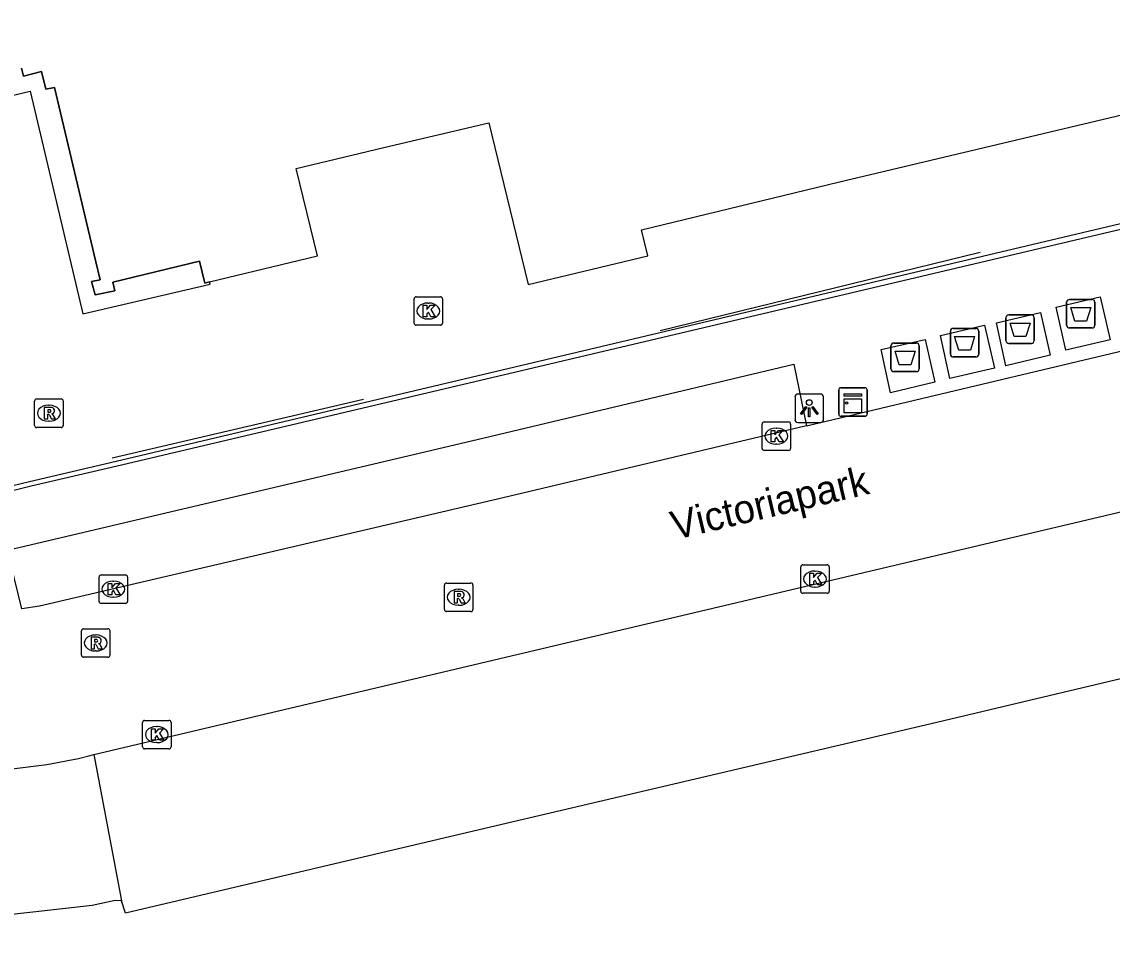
# Model space of a CAD drawing. Extents: x 160676 to 161153, y 383244 to 383713.
# Drawn here: x 160908.82 to 160947.04, y 383443.78 to 383475.88 of the extents above; entities that cross this region are included whole.
import ezdxf

# ---------------------------------------------------------------- set-up
doc = ezdxf.new("R2010")
doc.units = 0
for name, color, linetype in [('IMGEO_Afval_apart_plaats', 7, 'Continuous'), ('IMGEO_Kast', 7, 'Continuous'), ('IMGEO_Kolk', 7, 'Continuous'), ('IMGEO_Lichtpunt', 7, 'Continuous'), ('IMGEO_Lijnafwatering', 7, 'Continuous'), ('IMGEO_Muur', 7, 'Continuous'), ('IMGEO_Openbare_ruimte_label', 7, 'Continuous'), ('IMGEO_Pand', 7, 'Continuous'), ('IMGEO_Pand_overbouw', 7, 'Continuous'), ('IMGEO_Parkeervlak_gesloten', 7, 'Continuous'), ('IMGEO_Rijbaan_lokaal_gesloten', 7, 'Continuous'), ('IMGEO_Rioolput', 7, 'Continuous'), ('IMGEO_Voetpad_gesloten', 7, 'Continuous'), ('IMGEO_Voetpad_open', 7, 'Continuous')]:
    doc.layers.add(name, color=color, linetype=linetype)

msp = doc.modelspace()

# ---------------------------------------------------------------- linework, layer by layer
at = {"layer": 'IMGEO_Afval_apart_plaats'}
for p, q in [((160945.439, 383465.254), (160945.439, 383466.054)), ((160945.439, 383466.054), (160945.439, 383465.254)), ((160945.539, 383466.154), (160946.329, 383466.154)), ((160946.329, 383466.154), (160945.539, 383466.154)), ((160946.429, 383466.054), (160946.429, 383465.254)), ((160946.429, 383465.254), (160946.429, 383466.054)), ((160943.313, 383464.712), (160943.313, 383465.512)), ((160943.313, 383465.512), (160943.313, 383464.712)), ((160943.413, 383465.612), (160944.203, 383465.612)), ((160944.203, 383465.612), (160943.413, 383465.612)), ((160944.303, 383465.512), (160944.303, 383464.712)), ((160944.303, 383464.712), (160944.303, 383465.512)), ((160941.367, 383464.239), (160941.367, 383465.039)), ((160941.367, 383465.039), (160941.367, 383464.239)), ((160941.467, 383465.139), (160942.257, 383465.139)), ((160942.257, 383465.139), (160941.467, 383465.139)), ((160942.357, 383465.039), (160942.357, 383464.239)), ((160942.357, 383464.239), (160942.357, 383465.039)), ((160946.329, 383465.154), (160945.539, 383465.154)), ((160945.539, 383465.154), (160946.329, 383465.154)), ((160939.282, 383463.725), (160939.282, 383464.525)), ((160939.282, 383464.525), (160939.282, 383463.725)), ((160939.382, 383464.625), (160940.172, 383464.625)), ((160940.172, 383464.625), (160939.382, 383464.625)), ((160940.272, 383464.525), (160940.272, 383463.725)), ((160940.272, 383463.725), (160940.272, 383464.525)), ((160944.203, 383464.612), (160943.413, 383464.612)), ((160943.413, 383464.612), (160944.203, 383464.612)), ((160942.257, 383464.139), (160941.467, 383464.139)), ((160941.467, 383464.139), (160942.257, 383464.139)), ((160940.172, 383463.625), (160939.382, 383463.625)), ((160939.382, 383463.625), (160940.172, 383463.625))]:
    msp.add_line(p, q, dxfattribs=at)
for points in [[(160945.582, 383465.868), (160946.286, 383465.868), (160946.137, 383465.398), (160945.731, 383465.398), (160945.582, 383465.868)], [(160943.456, 383465.326), (160944.16, 383465.326), (160944.011, 383464.856), (160943.605, 383464.856), (160943.456, 383465.326)], [(160941.51, 383464.853), (160942.214, 383464.853), (160942.065, 383464.383), (160941.659, 383464.383), (160941.51, 383464.853)], [(160939.425, 383464.339), (160940.129, 383464.339), (160939.98, 383463.869), (160939.574, 383463.869), (160939.425, 383464.339)]]:
    msp.add_lwpolyline(points, dxfattribs=at)
for centre, start, end in [((160945.539, 383466.054), 90, 180), ((160945.539, 383466.054), 90, 180), ((160946.329, 383466.054), 0, 90), ((160946.329, 383466.054), 360, 90), ((160943.413, 383465.512), 90, 180), ((160943.413, 383465.512), 90, 180), ((160944.203, 383465.512), 0, 90), ((160944.203, 383465.512), 360, 90), ((160941.467, 383465.039), 90, 180), ((160941.467, 383465.039), 90, 180), ((160942.257, 383465.039), 0, 90), ((160942.257, 383465.039), 360, 90), ((160945.539, 383465.254), 180, 270), ((160945.539, 383465.254), 180, 270), ((160946.329, 383465.254), 270, 0), ((160946.329, 383465.254), 270, 0), ((160939.382, 383464.525), 90, 180), ((160939.382, 383464.525), 90, 180), ((160940.172, 383464.525), 0, 90), ((160940.172, 383464.525), 360, 90), ((160943.413, 383464.712), 180, 270), ((160943.413, 383464.712), 180, 270), ((160944.203, 383464.712), 270, 0), ((160944.203, 383464.712), 270, 0), ((160941.467, 383464.239), 180, 270), ((160941.467, 383464.239), 180, 270), ((160942.257, 383464.239), 270, 0), ((160942.257, 383464.239), 270, 0), ((160939.382, 383463.725), 180, 270), ((160939.382, 383463.725), 180, 270), ((160940.172, 383463.725), 270, 0), ((160940.172, 383463.725), 270, 0)]:
    msp.add_arc(centre, 0.1, start, end, dxfattribs=at)
at = {"layer": 'IMGEO_Kast'}
for p, q in [((160937.525, 383463.06), (160938.366, 383463.06)), ((160938.366, 383463.06), (160937.525, 383463.06)), ((160938.45, 383462.985), (160938.45, 383462.144)), ((160938.45, 383462.144), (160938.45, 383462.985)), ((160937.45, 383462.135), (160937.45, 383462.976)), ((160937.45, 383462.976), (160937.45, 383462.135)), ((160938.375, 383462.06), (160937.534, 383462.06)), ((160937.534, 383462.06), (160938.375, 383462.06))]:
    msp.add_line(p, q, dxfattribs=at)
for points in [[(160937.645, 383462.85), (160938.245, 383462.85), (160938.245, 383462.765), (160937.645, 383462.765), (160937.645, 383462.85)], [(160937.645, 383462.675), (160938.245, 383462.675), (160938.245, 383462.186), (160937.645, 383462.186), (160937.645, 383462.675)]]:
    msp.add_lwpolyline(points, dxfattribs=at)
msp.add_circle((160937.729, 383462.524), 0.0377, dxfattribs=at)
for centre, start, end in [((160937.528, 383462.982), 92.4484, 184.2845), ((160937.528, 383462.982), 92.4484, 184.2845), ((160938.372, 383462.982), 2.4484, 94.2845), ((160938.372, 383462.982), 2.4484, 94.2845), ((160937.528, 383462.138), 182.4484, 274.2845), ((160937.528, 383462.138), 182.4484, 274.2845), ((160938.372, 383462.138), 272.4484, 4.2845), ((160938.372, 383462.138), 272.4484, 4.2845)]:
    msp.add_arc(centre, 0.0779, start, end, dxfattribs=at)
at = {"layer": 'IMGEO_Kolk'}
for p, q in [((160922.567, 383465.323), (160922.567, 383466.175)), ((160922.642, 383466.249), (160923.494, 383466.249)), ((160923.568, 383466.175), (160923.568, 383465.323)), ((160923.055, 383466.029), (160923.08, 383466.029)), ((160923.078, 383465.469), (160923.053, 383465.469)), ((160923.494, 383465.249), (160922.642, 383465.249)), ((160934.841, 383461.864), (160935.693, 383461.864)), ((160934.766, 383460.938), (160934.766, 383461.79)), ((160935.254, 383461.644), (160935.279, 383461.644)), ((160935.767, 383461.79), (160935.767, 383460.938)), ((160935.277, 383461.084), (160935.252, 383461.084)), ((160935.693, 383460.864), (160934.841, 383460.864)), ((160911.601, 383456.505), (160912.453, 383456.505)), ((160936.119, 383455.934), (160936.119, 383456.786)), ((160936.194, 383456.86), (160937.046, 383456.86)), ((160936.607, 383456.64), (160936.632, 383456.64)), ((160937.12, 383456.786), (160937.12, 383455.934)), ((160911.526, 383455.579), (160911.526, 383456.431)), ((160912.014, 383456.285), (160912.039, 383456.285)), ((160912.527, 383456.431), (160912.527, 383455.579)), ((160912.037, 383455.725), (160912.012, 383455.725)), ((160937.046, 383455.86), (160936.194, 383455.86)), ((160936.63, 383456.08), (160936.605, 383456.08)), ((160912.453, 383455.505), (160911.601, 383455.505)), ((160913.049, 383450.484), (160913.049, 383451.336)), ((160913.124, 383451.41), (160913.976, 383451.41)), ((160913.537, 383451.19), (160913.562, 383451.19)), ((160914.05, 383451.336), (160914.05, 383450.484)), ((160913.976, 383450.41), (160913.124, 383450.41)), ((160913.56, 383450.63), (160913.535, 383450.63))]:
    msp.add_line(p, q, dxfattribs=at)
for points in [[(160922.567, 383465.323), (160922.567, 383466.175)], [(160922.642, 383466.249), (160923.494, 383466.249)], [(160923.568, 383466.175), (160923.568, 383465.323)], [(160922.888, 383465.949), (160923.011, 383465.949), (160923.011, 383465.798), (160923.141, 383465.949), (160923.305, 383465.949), (160923.159, 383465.798), (160923.312, 383465.549), (160923.16, 383465.549), (160923.075, 383465.713), (160923.011, 383465.646), (160923.011, 383465.549), (160922.888, 383465.549), (160922.888, 383465.949)], [(160923.494, 383465.249), (160922.642, 383465.249)], [(160934.841, 383461.864), (160935.693, 383461.864)], [(160934.766, 383460.938), (160934.766, 383461.79)], [(160935.087, 383461.564), (160935.21, 383461.564), (160935.21, 383461.413), (160935.34, 383461.564), (160935.504, 383461.564), (160935.358, 383461.413), (160935.511, 383461.164), (160935.359, 383461.164), (160935.274, 383461.328), (160935.21, 383461.261), (160935.21, 383461.164), (160935.087, 383461.164), (160935.087, 383461.564)], [(160935.767, 383461.79), (160935.767, 383460.938)], [(160935.693, 383460.864), (160934.841, 383460.864)], [(160911.601, 383456.505), (160912.453, 383456.505)], [(160936.119, 383455.934), (160936.119, 383456.786)], [(160936.194, 383456.86), (160937.046, 383456.86)], [(160936.44, 383456.56), (160936.563, 383456.56), (160936.563, 383456.409), (160936.693, 383456.56), (160936.857, 383456.56), (160936.711, 383456.409), (160936.864, 383456.16), (160936.712, 383456.16), (160936.627, 383456.324), (160936.563, 383456.257), (160936.563, 383456.16), (160936.44, 383456.16), (160936.44, 383456.56)], [(160937.12, 383456.786), (160937.12, 383455.934)], [(160911.526, 383455.579), (160911.526, 383456.431)], [(160911.847, 383456.205), (160911.97, 383456.205), (160911.97, 383456.054), (160912.1, 383456.205), (160912.264, 383456.205), (160912.118, 383456.054), (160912.271, 383455.805), (160912.119, 383455.805), (160912.034, 383455.969), (160911.97, 383455.902), (160911.97, 383455.805), (160911.847, 383455.805), (160911.847, 383456.205)], [(160912.527, 383456.431), (160912.527, 383455.579)], [(160937.046, 383455.86), (160936.194, 383455.86)], [(160912.453, 383455.505), (160911.601, 383455.505)], [(160913.049, 383450.484), (160913.049, 383451.336)], [(160913.124, 383451.41), (160913.976, 383451.41)], [(160914.05, 383451.336), (160914.05, 383450.484)], [(160913.37, 383451.11), (160913.493, 383451.11), (160913.493, 383450.959), (160913.623, 383451.11), (160913.787, 383451.11), (160913.641, 383450.959), (160913.794, 383450.71), (160913.642, 383450.71), (160913.557, 383450.874), (160913.493, 383450.807), (160913.493, 383450.71), (160913.37, 383450.71), (160913.37, 383451.11)], [(160913.976, 383450.41), (160913.124, 383450.41)]]:
    msp.add_lwpolyline(points, dxfattribs=at)
for centre, start, end in [((160922.644, 383466.173), 91.552, 178.448), ((160922.644, 383466.173), 91.552, 178.448), ((160923.492, 383466.173), 1.552, 88.448), ((160923.492, 383466.173), 1.552, 88.448), ((160922.644, 383465.325), 181.552, 268.448), ((160922.644, 383465.325), 181.552, 268.448), ((160923.492, 383465.325), 271.552, 358.448), ((160923.492, 383465.325), 271.552, 358.448), ((160934.843, 383461.788), 91.552, 178.448), ((160934.843, 383461.788), 91.552, 178.448), ((160935.691, 383461.788), 1.552, 88.448), ((160935.691, 383461.788), 1.552, 88.448), ((160934.843, 383460.94), 181.552, 268.448), ((160934.843, 383460.94), 181.552, 268.448), ((160935.691, 383460.94), 271.552, 358.448), ((160935.691, 383460.94), 271.552, 358.448), ((160911.603, 383456.429), 91.552, 178.448), ((160911.603, 383456.429), 91.552, 178.448), ((160912.451, 383456.429), 1.552, 88.448), ((160912.451, 383456.429), 1.552, 88.448), ((160936.196, 383456.784), 91.552, 178.448), ((160936.196, 383456.784), 91.552, 178.448), ((160937.044, 383456.784), 1.552, 88.448), ((160937.044, 383456.784), 1.552, 88.448), ((160936.196, 383455.936), 181.552, 268.448), ((160936.196, 383455.936), 181.552, 268.448), ((160937.044, 383455.936), 271.552, 358.448), ((160937.044, 383455.936), 271.552, 358.448), ((160911.603, 383455.581), 181.552, 268.448), ((160911.603, 383455.581), 181.552, 268.448), ((160912.451, 383455.581), 271.552, 358.448), ((160912.451, 383455.581), 271.552, 358.448), ((160913.126, 383451.334), 91.552, 178.448), ((160913.126, 383451.334), 91.552, 178.448), ((160913.974, 383451.334), 1.552, 88.448), ((160913.974, 383451.334), 1.552, 88.448), ((160913.126, 383450.486), 181.552, 268.448), ((160913.126, 383450.486), 181.552, 268.448), ((160913.974, 383450.486), 271.552, 358.448), ((160913.974, 383450.486), 271.552, 358.448)]:
    msp.add_arc(centre, 0.0765, start, end, dxfattribs=at)
for centre, major_axis, ratio, start_param, end_param in [((160923.054, 383465.749), (-0.387, 0.002), 0.722429, 4.712389, 7.853982), ((160923.079, 383465.749), (-0.39, 0.002), 0.717154, 1.570796, 4.712389), ((160935.253, 383461.364), (-0.387, 0.002), 0.722429, 4.712389, 7.853982), ((160935.278, 383461.364), (-0.39, 0.002), 0.717154, 1.570796, 4.712389), ((160936.606, 383456.36), (-0.387, 0.002), 0.722429, 4.712389, 7.853982), ((160936.631, 383456.36), (-0.39, 0.002), 0.717154, 1.570796, 4.712389), ((160912.013, 383456.005), (-0.387, 0.002), 0.722429, 4.712389, 7.853982), ((160912.038, 383456.005), (-0.39, 0.002), 0.717154, 1.570796, 4.712389), ((160913.536, 383450.91), (-0.387, 0.002), 0.722429, 4.712389, 7.853982), ((160913.561, 383450.91), (-0.39, 0.002), 0.717154, 1.570796, 4.712389)]:
    msp.add_ellipse(centre, major_axis=major_axis, ratio=ratio, start_param=start_param, end_param=end_param, dxfattribs=at)
at = {"layer": 'IMGEO_Lichtpunt'}
for p, q in [((160935.92, 383462.745), (160935.92, 383461.938)), ((160935.92, 383462.745), (160935.92, 383461.938)), ((160936.822, 383462.84), (160936.014, 383462.84)), ((160936.822, 383462.84), (160936.014, 383462.84)), ((160936.916, 383461.938), (160936.916, 383462.745)), ((160936.916, 383461.938), (160936.916, 383462.745)), ((160936.014, 383461.844), (160936.822, 383461.844)), ((160936.014, 383461.844), (160936.822, 383461.844))]:
    msp.add_line(p, q, dxfattribs=at)
for points in [[(160936.294, 383462.409), (160936.333, 383462.381), (160936.145, 383462.119), (160936.107, 383462.146), (160936.294, 383462.409)], [(160936.396, 383462.361), (160936.443, 383462.361), (160936.443, 383462.039), (160936.396, 383462.039), (160936.396, 383462.361)], [(160936.506, 383462.381), (160936.544, 383462.408), (160936.731, 383462.146), (160936.692, 383462.118), (160936.506, 383462.381)]]:
    msp.add_lwpolyline(points, dxfattribs=at)
msp.add_circle((160936.419, 383462.543), 0.0994, dxfattribs=at)
for centre, start, end in [((160936.014, 383462.745), 90, 180), ((160936.014, 383462.745), 90, 180), ((160936.822, 383462.745), 0, 90), ((160936.822, 383462.745), 0, 90), ((160936.014, 383461.938), 180, 270), ((160936.014, 383461.938), 180, 270), ((160936.822, 383461.938), 270, 0), ((160936.822, 383461.938), 270, 360)]:
    msp.add_arc(centre, 0.0946, start, end, dxfattribs=at)
at = {"layer": 'IMGEO_Lijnafwatering'}
for points in [[(160931.192, 383465.07), (160942.413, 383467.815)], [(160911.987, 383460.608), (160920.79, 383462.662)]]:
    msp.add_lwpolyline(points, dxfattribs=at)
at = {"layer": 'IMGEO_Muur'}
for points in [[(160961.939, 383472.274), (160962.002, 383472.066), (160912.316, 383460.345), (160909.143, 383459.613), (160907.173, 383459.127), (160907.11, 383459.309)], [(160908.505, 383459.64), (160909.084, 383459.778), (160912.322, 383460.539), (160961.939, 383472.274)]]:
    msp.add_lwpolyline(points, dxfattribs=at)
at = {"layer": 'IMGEO_Pand'}
msp.add_lwpolyline([(160908.807, 383474.261), (160908.877, 383473.979), (160909.508, 383474.136), (160909.663, 383473.515), (160909.96, 383473.58), (160911.415, 383467.471), (160911.564, 383466.845), (160911.267, 383466.778), (160911.394, 383466.316), (160912.074, 383466.461), (160912.006, 383466.754), (160915.052, 383467.496), (160915.238, 383466.729), (160915.401, 383466.768), (160919.181, 383467.683), (160918.441, 383470.74), (160921.51, 383471.475), (160925.187, 383472.344), (160926.562, 383466.682), (160930.76, 383467.683), (160930.542, 383468.594), (160937.433, 383470.262), (160961.1, 383475.879)], dxfattribs=at)
at = {"layer": 'IMGEO_Pand_overbouw'}
msp.add_lwpolyline([(160876.374, 383465.682), (160909.108, 383473.445), (160910.957, 383465.645), (160915.419, 383466.694), (160915.401, 383466.768), (160915.238, 383466.729), (160915.052, 383467.496), (160912.006, 383466.754), (160912.074, 383466.461), (160911.394, 383466.316), (160911.267, 383466.778), (160911.564, 383466.845), (160911.415, 383467.471), (160909.96, 383473.58), (160909.663, 383473.515), (160909.508, 383474.136), (160908.877, 383473.979), (160908.807, 383474.261)], dxfattribs=at)
at = {"layer": 'IMGEO_Parkeervlak_gesloten'}
msp.add_lwpolyline([(161010.691, 383452.436), (161010.431, 383452.481), (161007.919, 383451.629), (161008.407, 383449.21), (161000.128, 383447.369), (160985.135, 383443.735), (160969.602, 383440.105), (160961.401, 383438.272), (160959.945, 383443.924), (160957.181, 383455.143), (160948.323, 383453.092), (160940.889, 383451.334), (160925.647, 383447.762), (160912.456, 383444.655), (160912.313, 383445.09)], dxfattribs=at)
at = {"layer": 'IMGEO_Rijbaan_lokaal_gesloten'}
for points in [[(160911.346, 383450.209), (160931.555, 383454.985), (160949.112, 383459.134), (160966.645, 383463.289), (160980.701, 383466.632), (160995.466, 383470.147), (161006.042, 383472.607)], [(160936.322, 383461.732), (160965.222, 383468.589)], [(160936.322, 383461.732), (160925.692, 383459.21), (160909.438, 383455.409), (160908.819, 383455.316)], [(160911.167, 383450.167), (160911.346, 383450.209)]]:
    msp.add_lwpolyline(points, dxfattribs=at)
msp.add_arc((160907.048, 383466.594), 16.936, 263.7554, 284.0756, dxfattribs=at)
at = {"layer": 'IMGEO_Rioolput'}
for p, q in [((160909.344, 383462.668), (160910.196, 383462.668)), ((160909.269, 383461.742), (160909.269, 383462.594)), ((160909.757, 383462.448), (160909.782, 383462.448)), ((160910.27, 383462.594), (160910.27, 383461.742)), ((160909.78, 383461.888), (160909.755, 383461.888)), ((160910.196, 383461.668), (160909.344, 383461.668)), ((160923.631, 383455.295), (160923.631, 383456.147)), ((160923.706, 383456.221), (160924.558, 383456.221)), ((160924.632, 383456.147), (160924.632, 383455.295)), ((160924.119, 383456.001), (160924.144, 383456.001)), ((160924.142, 383455.441), (160924.117, 383455.441)), ((160924.558, 383455.221), (160923.706, 383455.221)), ((160910.984, 383454.62), (160911.836, 383454.62)), ((160910.909, 383453.694), (160910.909, 383454.546)), ((160911.397, 383454.4), (160911.422, 383454.4)), ((160911.91, 383454.546), (160911.91, 383453.694)), ((160911.42, 383453.84), (160911.395, 383453.84)), ((160911.836, 383453.62), (160910.984, 383453.62))]:
    msp.add_line(p, q, dxfattribs=at)
for points in [[(160909.344, 383462.668), (160910.196, 383462.668)], [(160909.269, 383461.742), (160909.269, 383462.594)], [(160909.858, 383462.366), (160909.606, 383462.368), (160909.606, 383461.968)], [(160909.784, 383462.287), (160909.73, 383462.287), (160909.73, 383462.206)], [(160910.27, 383462.594), (160910.27, 383461.742)], [(160909.606, 383461.968), (160909.73, 383461.968), (160909.73, 383462.13), (160909.741, 383462.13)], [(160909.73, 383462.206), (160909.782, 383462.206)], [(160909.788, 383462.101), (160909.859, 383461.968), (160909.999, 383461.968), (160909.934, 383462.094)], [(160910.196, 383461.668), (160909.344, 383461.668)], [(160923.631, 383455.295), (160923.631, 383456.147)], [(160923.706, 383456.221), (160924.558, 383456.221)], [(160924.632, 383456.147), (160924.632, 383455.295)], [(160924.22, 383455.919), (160923.968, 383455.921), (160923.968, 383455.521)], [(160924.146, 383455.84), (160924.092, 383455.84), (160924.092, 383455.759)], [(160924.092, 383455.759), (160924.144, 383455.759)], [(160923.968, 383455.521), (160924.092, 383455.521), (160924.092, 383455.683), (160924.103, 383455.683)], [(160924.15, 383455.654), (160924.221, 383455.521), (160924.361, 383455.521), (160924.296, 383455.647)], [(160924.558, 383455.221), (160923.706, 383455.221)], [(160910.984, 383454.62), (160911.836, 383454.62)], [(160910.909, 383453.694), (160910.909, 383454.546)], [(160911.498, 383454.318), (160911.246, 383454.32), (160911.246, 383453.92)], [(160911.424, 383454.239), (160911.37, 383454.239), (160911.37, 383454.158)], [(160911.91, 383454.546), (160911.91, 383453.694)], [(160911.246, 383453.92), (160911.37, 383453.92), (160911.37, 383454.082), (160911.381, 383454.082)], [(160911.37, 383454.158), (160911.422, 383454.158)], [(160911.428, 383454.053), (160911.499, 383453.92), (160911.639, 383453.92), (160911.574, 383454.046)], [(160911.836, 383453.62), (160910.984, 383453.62)]]:
    msp.add_lwpolyline(points, dxfattribs=at)
for centre, radius, start, end in [((160909.346, 383462.592), 0.0765, 91.552, 178.448), ((160909.346, 383462.592), 0.0765, 91.552, 178.448), ((160910.194, 383462.592), 0.0765, 1.552, 88.448), ((160910.194, 383462.592), 0.0765, 1.552, 88.448), ((160909.79, 383462.191), 0.0964, 77.0061, 93.1865), ((160909.804, 383462.248), 0.0378, 276.6634, 79.6772), ((160909.857, 383462.256), 0.109, 350.3612, 89.416), ((160909.855, 383462.256), 0.112, 277.5842, 350.9817), ((160909.74, 383462.077), 0.0533, 26.0293, 88.6989), ((160909.766, 383462.395), 0.19, 274.7715, 282.9687), ((160909.839, 383462.041), 0.108, 29.5134, 73.7905), ((160909.346, 383461.744), 0.0765, 181.552, 268.448), ((160909.346, 383461.744), 0.0765, 181.552, 268.448), ((160910.194, 383461.744), 0.0765, 271.552, 358.448), ((160910.194, 383461.744), 0.0765, 271.552, 358.448), ((160923.708, 383456.145), 0.0765, 91.552, 178.448), ((160923.708, 383456.145), 0.0765, 91.552, 178.448), ((160924.556, 383456.145), 0.0765, 1.552, 88.448), ((160924.556, 383456.145), 0.0765, 1.552, 88.448), ((160924.128, 383455.948), 0.19, 274.7715, 282.9687), ((160924.152, 383455.744), 0.0964, 77.0061, 93.1865), ((160924.166, 383455.801), 0.0378, 276.6634, 79.6772), ((160924.219, 383455.809), 0.109, 350.3612, 89.416), ((160924.217, 383455.809), 0.112, 277.5842, 350.9817), ((160924.102, 383455.63), 0.0533, 26.0293, 88.6989), ((160924.201, 383455.594), 0.108, 29.5134, 73.7905), ((160923.708, 383455.297), 0.0765, 181.552, 268.448), ((160923.708, 383455.297), 0.0765, 181.552, 268.448), ((160924.556, 383455.297), 0.0765, 271.552, 358.448), ((160924.556, 383455.297), 0.0765, 271.552, 358.448), ((160910.986, 383454.544), 0.0765, 91.552, 178.448), ((160910.986, 383454.544), 0.0765, 91.552, 178.448), ((160911.834, 383454.544), 0.0765, 1.552, 88.448), ((160911.834, 383454.544), 0.0765, 1.552, 88.448), ((160911.43, 383454.143), 0.0964, 77.0061, 93.1865), ((160911.444, 383454.2), 0.0378, 276.6634, 79.6772), ((160911.497, 383454.208), 0.109, 350.3612, 89.416), ((160911.495, 383454.208), 0.112, 277.5842, 350.9817), ((160911.38, 383454.029), 0.0533, 26.0293, 88.6989), ((160911.406, 383454.347), 0.19, 274.7715, 282.9687), ((160911.479, 383453.993), 0.108, 29.5134, 73.7905), ((160910.986, 383453.696), 0.0765, 181.552, 268.448), ((160910.986, 383453.696), 0.0765, 181.552, 268.448), ((160911.834, 383453.696), 0.0765, 271.552, 358.448), ((160911.834, 383453.696), 0.0765, 271.552, 358.448)]:
    msp.add_arc(centre, radius, start, end, dxfattribs=at)
for centre, major_axis, ratio, start_param, end_param in [((160909.756, 383462.168), (-0.387, 0.002), 0.722429, 4.712389, 7.853982), ((160909.781, 383462.168), (-0.39, 0.002), 0.717154, 1.570796, 4.712389), ((160924.118, 383455.721), (-0.387, 0.002), 0.722429, 4.712389, 7.853982), ((160924.143, 383455.721), (-0.39, 0.002), 0.717154, 1.570796, 4.712389), ((160911.396, 383454.12), (-0.387, 0.002), 0.722429, 4.712389, 7.853982), ((160911.421, 383454.12), (-0.39, 0.002), 0.717154, 1.570796, 4.712389)]:
    msp.add_ellipse(centre, major_axis=major_axis, ratio=ratio, start_param=start_param, end_param=end_param, dxfattribs=at)
at = {"layer": 'IMGEO_Voetpad_gesloten'}
for points in [[(160946.62, 383466.242), (160946.967, 383464.739), (160945.409, 383464.373), (160945.077, 383465.883), (160946.62, 383466.242)], [(160944.521, 383465.7), (160944.868, 383464.197), (160943.31, 383463.831), (160942.978, 383465.34), (160944.521, 383465.7)], [(160942.562, 383465.255), (160942.908, 383463.752), (160941.35, 383463.386), (160941.019, 383464.896), (160942.562, 383465.255)], [(160940.477, 383464.755), (160940.823, 383463.251), (160939.265, 383462.885), (160938.934, 383464.395), (160940.477, 383464.755)]]:
    msp.add_lwpolyline(points, dxfattribs=at)
at = {"layer": 'IMGEO_Voetpad_open'}
for points in [[(160908.819, 383455.316), (160908.315, 383457.371), (160925.023, 383461.307), (160935.883, 383463.884), (160936.322, 383461.732)], [(160911.346, 383450.209), (160912.313, 383445.09)], [(160912.313, 383445.09), (160912.097, 383445.102), (160911.285, 383444.92), (160908.049, 383444.567), (160904.275, 383444.678), (160902.028, 383444.954), (160902.501, 383446.376), (160901.449, 383446.503), (160900.213, 383446.777)]]:
    msp.add_lwpolyline(points, dxfattribs=at)

# ---------------------------------------------------------------- texts
at = {"layer": 'IMGEO_Openbare_ruimte_label'}
msp.add_text('Victoriapark', height=1, rotation=13.2996, dxfattribs=at).set_placement((160931.705, 383457.729))

doc.saveas('drawing.dxf')
